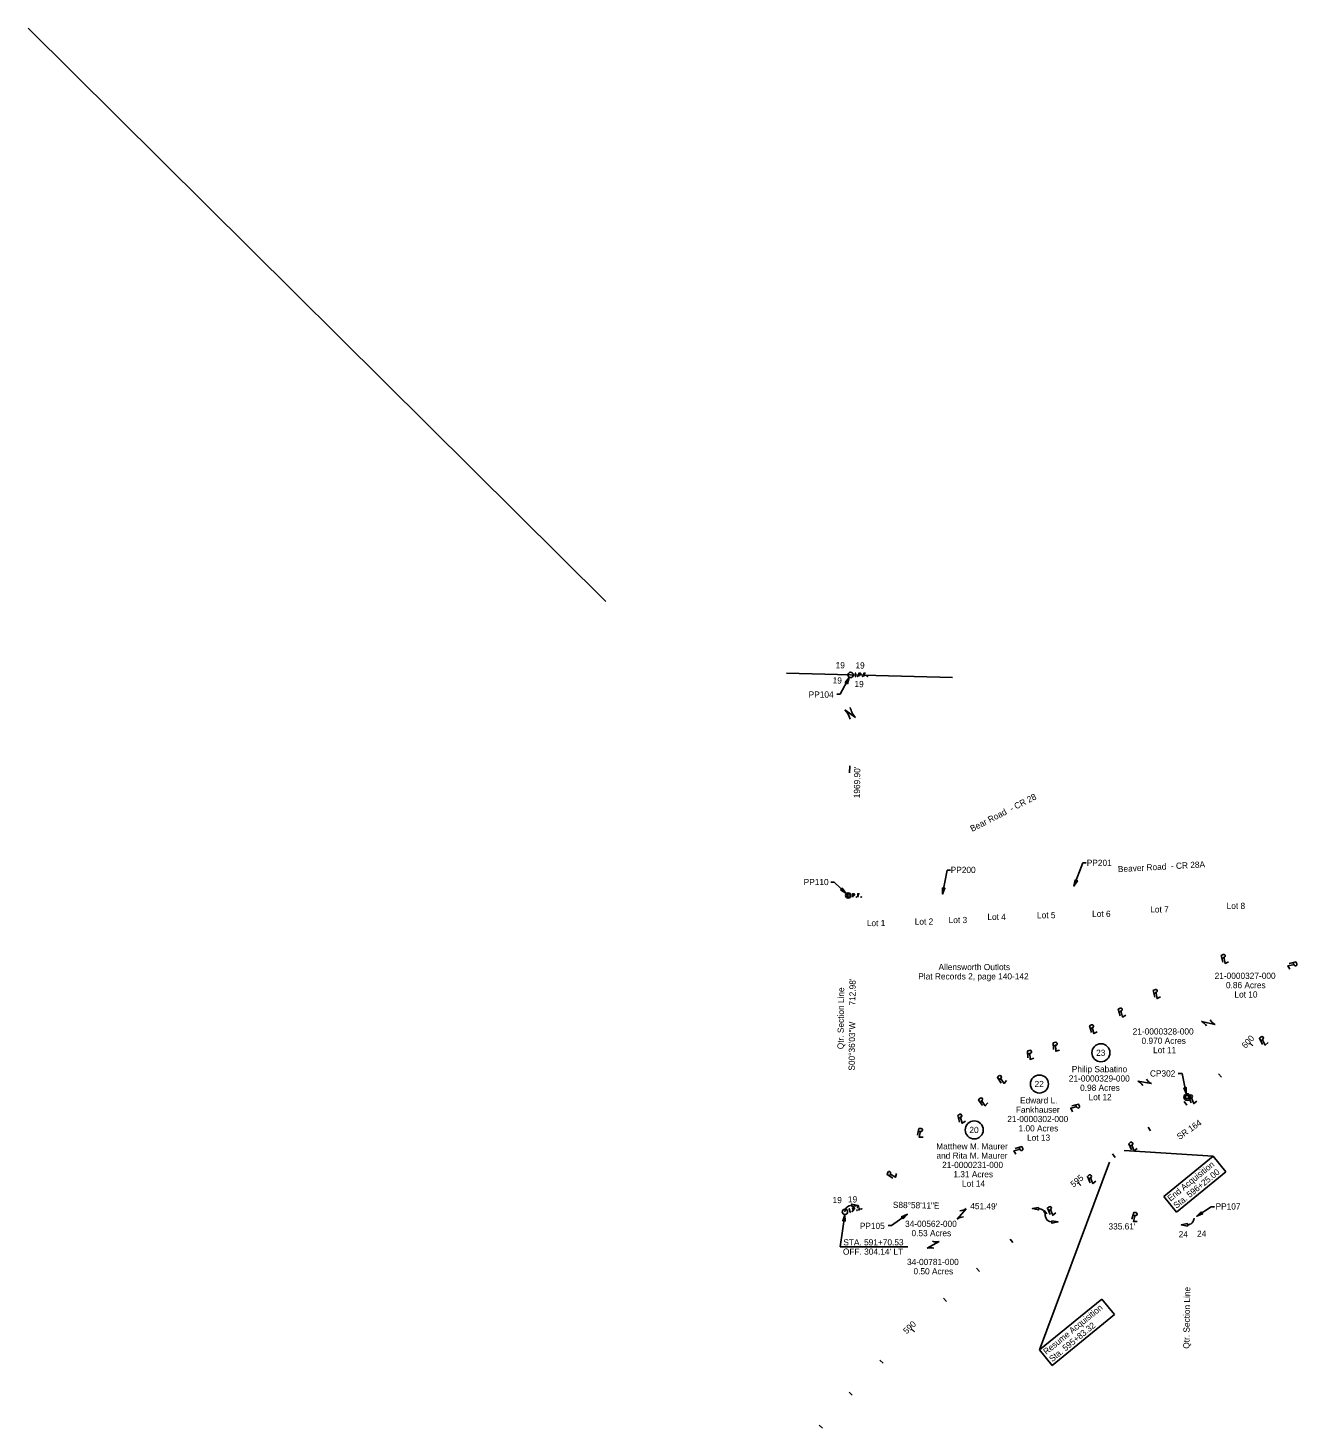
# Model space of a CAD drawing. Extents: x 250163 to 255971, y 441830 to 446572.
# Drawn here: x 250163 to 253023, y 443416 to 446572 of the extents above; entities that cross this region are included whole.
import ezdxf

# ---------------------------------------------------------------- set-up
doc = ezdxf.new("R2010")
doc.units = 0
for name, color, linetype in [('_CIVIL_CONSTRUCTION', 7, 'Continuous'), ('Default', 7, 'Continuous'), ('DV_X_County_Line', 7, 'Continuous'), ('DV_X_Section_VMS_Line', 7, 'Continuous'), ('PF_X_Ground_Line', 7, 'Continuous'), ('RW_P_Esmt_SH', 7, 'Continuous'), ('SH_Text', 7, 'Continuous'), ('SV_X_Text', 7, 'Continuous')]:
    doc.layers.add(name, color=color, linetype=linetype)

msp = doc.modelspace()

# ---------------------------------------------------------------- linework, layer by layer
at = {"layer": '_CIVIL_CONSTRUCTION'}
for p, q in [((252854.2, 444474.2), (252860, 444477.2)), ((252859.2, 444473.3), (252859.2, 444473.3)), ((253013.1, 444460.2), (253013.1, 444460.2)), ((253014, 444465.2), (253017, 444459.4)), ((252701, 444395.2), (252706.8, 444398.1)), ((252706, 444394.2), (252706, 444394.2)), ((252622.4, 444353.1), (252628, 444356.3)), ((252627.4, 444352.4), (252627.4, 444352.4)), ((252808.1, 444332.7), (252838.6, 444325.9)), ((252823.4, 444329.3), (252823.4, 444329.3)), ((252557.7, 444315.6), (252563.3, 444318.8)), ((252562.8, 444314.9), (252562.8, 444314.9)), ((252474.4, 444277.3), (252480.6, 444279.2)), ((252479.2, 444275.5), (252479.2, 444275.5)), ((252941.9, 444288.1), (252946.7, 444292.4)), ((252946.9, 444288.5), (252946.9, 444288.5)), ((252416.5, 444258.8), (252422.6, 444260.8)), ((252421.2, 444257.1), (252421.2, 444257.1)), ((252352.2, 444200.3), (252356.3, 444205.3)), ((252357.1, 444201.4), (252357.1, 444201.4)), ((252664.5, 444198.1), (252695.2, 444192.3)), ((252679.9, 444195.2), (252679.9, 444195.2)), ((252309.6, 444149.6), (252313.8, 444154.6)), ((252314.6, 444150.7), (252314.6, 444150.7)), ((252523.2, 444139.5), (252523.2, 444139.5)), ((252523.9, 444144.5), (252527.1, 444138.9)), ((252781.3, 444156.9), (252786.4, 444160.9)), ((252786.4, 444156.9), (252786.4, 444156.9)), ((252260.6, 444113.7), (252266.2, 444117)), ((252265.6, 444113.1), (252265.6, 444113.1)), ((252169.8, 444084.3), (252176.2, 444084.6)), ((252174, 444081.4), (252174, 444081.4)), ((252395.4, 444043.5), (252395.4, 444043.5)), ((252396, 444048.5), (252399.3, 444042.9)), ((252647.1, 444050.5), (252652.2, 444054.5)), ((252652.2, 444050.5), (252652.2, 444050.5)), ((252105.4, 443983.8), (252107.2, 443990)), ((252109.5, 443986.7), (252109.5, 443986.7)), ((252554, 443976.6), (252559.1, 443980.7)), ((252559.1, 443976.7), (252559.1, 443976.7)), ((252257.3, 443886.9), (252277.7, 443910.5)), ((252267.5, 443898.7), (252267.5, 443898.7)), ((252463.8, 443905.2), (252468.9, 443909.2)), ((252468.8, 443905.2), (252468.8, 443905.2)), ((252653.4, 443894.9), (252659.9, 443894.8)), ((252657.3, 443891.7), (252657.3, 443891.7)), ((252189.8, 443821.3), (252217, 443836.7)), ((252203.4, 443829), (252203.4, 443829))]:
    msp.add_line(p, q, dxfattribs=at)
for points in [[(252856, 444466.2), (252852.7, 444481.1), (252857.3, 444483.5)], [(252858.2, 444478.1), (252861.4, 444463.2), (252869.2, 444467.2)], [(253017.9, 444461.2), (253003, 444457.9), (253007, 444450.1)], [(253005.9, 444463.3), (253020.9, 444466.7), (253023.3, 444462.1)], [(252702.8, 444387.1), (252699.5, 444402.1), (252704.1, 444404.5)], [(252705, 444399.1), (252708.2, 444384.2), (252716, 444388.2)], [(252624.6, 444345.1), (252620.5, 444359.9), (252625, 444362.5)], [(252626.2, 444357.2), (252630.2, 444342.4), (252637.7, 444346.8)], [(252559.9, 444307.7), (252555.9, 444322.4), (252560.3, 444325)], [(252561.5, 444319.7), (252565.5, 444305), (252573.1, 444309.3)], [(252945.6, 444280.8), (252938.7, 444294.5), (252942.5, 444297.9)], [(252416.9, 444250.6), (252416.1, 444265.9), (252421, 444267.5)], [(252474.8, 444269), (252474, 444284.3), (252479, 444285.9)], [(252479, 444280.5), (252479.7, 444265.2), (252488, 444267.8)], [(252944.7, 444292.9), (252951.6, 444279.3), (252958.1, 444285.1)], [(252421, 444262.1), (252421.8, 444246.8), (252430.1, 444249.4)], [(252356.9, 444193.6), (252348.1, 444206.1), (252351.4, 444210.1)], [(252354.3, 444205.5), (252363.1, 444192.9), (252368.7, 444199.6)], [(252314.4, 444142.9), (252305.5, 444155.4), (252308.8, 444159.4)], [(252311.8, 444154.8), (252320.5, 444142.2), (252326.2, 444148.9)], [(252528, 444140.7), (252513.3, 444136.7), (252517.7, 444129.1)], [(252515.9, 444142.3), (252530.7, 444146.4), (252533.3, 444141.9)], [(252784.6, 444149.3), (252778.5, 444163.4), (252782.5, 444166.6)], [(252784.5, 444161.5), (252790.6, 444147.5), (252797.4, 444152.9)], [(252262.9, 444105.8), (252258.6, 444120.5), (252263.1, 444123.2)], [(252264.3, 444117.9), (252268.5, 444103.2), (252276, 444107.6)], [(252168.1, 444076.2), (252171.2, 444091.2), (252176.3, 444091.5)], [(252175, 444086.2), (252171.9, 444071.3), (252180.6, 444071.8)], [(252400.2, 444044.8), (252385.4, 444040.7), (252389.9, 444033.2)], [(252388.1, 444046.3), (252402.8, 444050.5), (252405.5, 444046)], [(252650.4, 444042.9), (252644.3, 444057), (252648.3, 444060.2)], [(252650.3, 444055.1), (252656.3, 444041.1), (252663.2, 444046.5)], [(252112.4, 443979.5), (252099.3, 443987.4), (252100.8, 443992.4)], [(252105.3, 443989.4), (252118.3, 443981.4), (252120.8, 443989.7)], [(252557.3, 443969.1), (252551.1, 443983.1), (252555.2, 443986.4)], [(252557.1, 443981.3), (252563.2, 443967.2), (252570, 443972.7)], [(252467.1, 443897.7), (252460.9, 443911.7), (252465, 443914.9)], [(252466.9, 443909.8), (252473, 443895.8), (252479.8, 443901.2)], [(252651.1, 443887), (252655.3, 443901.7), (252660.5, 443901.6)], [(252658.8, 443896.5), (252654.5, 443881.8), (252663.3, 443881.6)]]:
    msp.add_lwpolyline(points, dxfattribs=at)
for centre, radius, start, end in [((252858.4, 444480.2), 3.45, 297.7561, 108.6133), ((253020, 444461), 3.45, 207.9768, 18.8339), ((252705.2, 444401.2), 3.45, 297.7561, 108.6133), ((252626.2, 444359.3), 3.45, 300.5673, 111.4244), ((252796.2, 444308.9), 26.7, 30.8565, 63.4991), ((252850.5, 444349.8), 26.7, 210.8565, 243.4991), ((252561.6, 444321.8), 3.45, 300.5673, 111.4244), ((252944.4, 444295), 3.45, 312.048, 122.9051), ((252421.6, 444264.1), 3.45, 288.0957, 98.9528), ((252479.5, 444282.5), 3.45, 288.0957, 98.9528), ((252353.7, 444207.5), 3.45, 320.4702, 131.3273), ((252706.3, 444216.6), 26.7, 212.9302, 245.5727), ((252653.5, 444173.8), 26.7, 32.9302, 65.5727), ((252311.1, 444156.8), 3.45, 320.4702, 131.3273), ((252530.1, 444140.7), 3.45, 210.8545, 21.7116), ((252784.3, 444163.6), 3.45, 308.8749, 119.732), ((252264.4, 444120), 3.45, 301.2644, 112.1215), ((252176, 444088.1), 3.45, 273.8756, 84.7328), ((252402.3, 444044.7), 3.45, 210.9924, 21.8495), ((252650, 444057.2), 3.45, 308.8749, 119.732), ((252103.9, 443990.9), 3.45, 344.0044, 154.8615), ((252556.9, 443983.4), 3.45, 308.8749, 119.732), ((252272.7, 443865.1), 26.7, 92.6643, 125.3068), ((252262.3, 443932.3), 26.7, 272.6643, 305.3068), ((252466.7, 443911.9), 3.45, 308.7883, 119.6454), ((252659.9, 443898.2), 3.45, 269.4408, 80.2979), ((252197, 443795.6), 26.7, 72.9148, 105.5574), ((252209.9, 443862.4), 26.7, 252.9148, 285.5574)]:
    msp.add_arc(centre, radius, start, end, dxfattribs=at)
at = {"layer": 'DV_X_County_Line'}
for points in [[(252013.1, 443909.9), (252014.8, 443910.4)], [(252016.1, 443902.5), (252014, 443910.2)], [(252015.2, 443902.2), (252016.9, 443902.7)], [(252020.4, 443904.7), (252020.7, 443904.8), (252020.9, 443904.7), (252021.1, 443904.5), (252021.2, 443904.2), (252021.1, 443903.9), (252021, 443903.8), (252020.7, 443903.7), (252020.5, 443903.8), (252020.3, 443904), (252020.2, 443904.3), (252020.3, 443904.6), (252020.4, 443904.7)], [(252023.6, 443904.5), (252021.5, 443912.2), (252024.1, 443912.9), (252024.4, 443912.9), (252024.8, 443912.9), (252025, 443912.8), (252025.2, 443912.7), (252025.5, 443912.5), (252025.7, 443912.2), (252025.9, 443911.8), (252026.1, 443911.1), (252026.2, 443910.8), (252026.2, 443910.4), (252026.1, 443909.9), (252025.9, 443909.7), (252025.8, 443909.5), (252025.5, 443909.3), (252025.1, 443909.1), (252022.6, 443908.5)], [(252031.3, 443907.7), (252031.6, 443907.8), (252031.7, 443907.7), (252032, 443907.5), (252032.1, 443907.2), (252032, 443906.9), (252031.8, 443906.7), (252031.6, 443906.7), (252031.4, 443906.7), (252031.1, 443906.9), (252031.1, 443907.2), (252031.2, 443907.5), (252031.3, 443907.7)], [(252036.2, 443915.6), (252036.1, 443915.7), (252035.9, 443915.8), (252035.4, 443915.8), (252034.7, 443915.8), (252034.3, 443915.7), (252034.2, 443915.6), (252033.5, 443915.3), (252033, 443914.7), (252032.8, 443914.2), (252032.8, 443913.6), (252032.9, 443913.3), (252033.1, 443912.8), (252033.7, 443912.5), (252037.1, 443911.5), (252037.4, 443911.3), (252037.6, 443911.1), (252037.8, 443910.8), (252037.9, 443910.4), (252038, 443910), (252038, 443909.8), (252038, 443909.4), (252037.9, 443909.2), (252037.9, 443908.9), (252037.7, 443908.7), (252037.6, 443908.6), (252037.4, 443908.4), (252037.3, 443908.3), (252036.8, 443908.1), (252036.1, 443907.9), (252035.6, 443907.9), (252034.8, 443908.1), (252034.2, 443908.4)], [(252041.8, 443910.5), (252042.1, 443910.6), (252042.3, 443910.5), (252042.5, 443910.3), (252042.6, 443910), (252042.5, 443909.7), (252042.4, 443909.6), (252042.1, 443909.5), (252041.9, 443909.6), (252041.7, 443909.8), (252041.6, 443910.1), (252041.7, 443910.4), (252041.8, 443910.5)]]:
    msp.add_lwpolyline(points, dxfattribs=at)
msp.add_circle((252004.4, 443903.4), 6, dxfattribs=at)
at = {"layer": 'DV_X_Section_VMS_Line'}
for p, q in [((251872.6, 445117.6), (252246.6, 445107.6)), ((252015, 444909), (252014.8, 444893.2))]:
    msp.add_line(p, q, dxfattribs=at)
at = {"layer": 'PF_X_Ground_Line'}
for points in [[(252027.2, 445117.7), (252029, 445117.7)], [(252028.1, 445109.7), (252028.1, 445117.7)], [(252035.9, 445109.7), (252035.9, 445117.7), (252038.6, 445117.7), (252038.8, 445117.7), (252039.2, 445117.5), (252039.4, 445117.4), (252039.6, 445117.3), (252039.8, 445117), (252039.9, 445116.6), (252040.1, 445116.1), (252040.1, 445115.4), (252040, 445115.1), (252039.9, 445114.8), (252039.7, 445114.3), (252039.4, 445114.1), (252039.3, 445114), (252039, 445113.9), (252038.6, 445113.8), (252035.9, 445113.8)], [(252051, 445117.7), (252047.2, 445117.7), (252047.2, 445109.7)], [(252027.2, 445109.7), (252029, 445109.7)], [(252032.9, 445110.8), (252033.2, 445110.8), (252033.3, 445110.7), (252033.5, 445110.4), (252033.5, 445110.1), (252033.3, 445109.8), (252033.2, 445109.7), (252032.9, 445109.7), (252032.7, 445109.8), (252032.6, 445110.1), (252032.6, 445110.4), (252032.7, 445110.7), (252032.9, 445110.8)], [(252044.1, 445110.8), (252044.4, 445110.8), (252044.6, 445110.7), (252044.7, 445110.4), (252044.7, 445110.1), (252044.6, 445109.8), (252044.4, 445109.7), (252044.1, 445109.7), (252044, 445109.8), (252043.8, 445110.1), (252043.8, 445110.4), (252044, 445110.7), (252044.1, 445110.8)], [(252047.2, 445113.8), (252049.9, 445113.8)], [(252054.9, 445110.8), (252055.2, 445110.8), (252055.3, 445110.7), (252055.5, 445110.4), (252055.5, 445110.1), (252055.3, 445109.8), (252055.2, 445109.7), (252054.9, 445109.7), (252054.7, 445109.8), (252054.6, 445110.1), (252054.6, 445110.4), (252054.7, 445110.7), (252054.9, 445110.8)], [(252021.9, 444612.4), (252021.9, 444620.4), (252024.6, 444620.4), (252024.8, 444620.3), (252025.2, 444620.2), (252025.4, 444620.1), (252025.5, 444619.9), (252025.8, 444619.6), (252025.9, 444619.3), (252026, 444618.8), (252026, 444618), (252026, 444617.8), (252025.9, 444617.4), (252025.7, 444617), (252025.4, 444616.8), (252025.3, 444616.7), (252025, 444616.5), (252024.6, 444616.5), (252021.9, 444616.5)], [(252030.1, 444613.4), (252030.4, 444613.4), (252030.6, 444613.3), (252030.7, 444613.1), (252030.7, 444612.7), (252030.6, 444612.5), (252030.4, 444612.4), (252030.1, 444612.4), (252030, 444612.5), (252029.8, 444612.7), (252029.8, 444613.1), (252030, 444613.3), (252030.1, 444613.4)], [(252037, 444620.4), (252033.2, 444620.4), (252033.2, 444612.4)], [(252033.2, 444616.5), (252035.9, 444616.5)], [(252040.9, 444613.4), (252041.1, 444613.4), (252041.3, 444613.3), (252041.5, 444613.1), (252041.5, 444612.7), (252041.3, 444612.5), (252041.1, 444612.4), (252040.9, 444612.4), (252040.7, 444612.5), (252040.5, 444612.7), (252040.5, 444613.1), (252040.7, 444613.3), (252040.9, 444613.4)]]:
    msp.add_lwpolyline(points, dxfattribs=at)
for centre, radius in [((252017.1, 445113.7), 6), ((252011.9, 444616.4), 6), ((252011.9, 444616.4), 2.47), ((252775.7, 444162.1), 7.5), ((252775.7, 444162.1), 4)]:
    msp.add_circle(centre, radius, dxfattribs=at)
at = {"layer": 'RW_P_Esmt_SH'}
msp.add_line((252004.4, 445034.6), (252028, 445017.3), dxfattribs=at)
for centre, radius, start, end in [((251967.7, 445000.1), 50.4, 16.1133, 43.2192), ((252070.5, 445053.3), 55.7, 193.5159, 220.2851)]:
    msp.add_arc(centre, radius, start, end, dxfattribs=at)
at = {"layer": 'SH_Text'}
for p, q in [((251465.3, 445279.2), (250162.7, 446571.8)), ((252923.7, 444277.4), (252916.3, 444284.1)), ((252852.9, 444206.8), (252846.3, 444214.3)), ((252775.1, 444144.1), (252769.3, 444152.2)), ((252693.5, 444086.3), (252687.6, 444094.4)), ((252613.8, 444026), (252607.6, 444033.8)), ((252536.2, 443962.9), (252529.7, 443970.5)), ((252459.7, 443898.5), (252453.2, 443906.2)), ((252383.1, 443834.1), (252376.7, 443841.7)), ((252307.5, 443768.7), (252300.9, 443776.1)), ((252233.5, 443701.5), (252226.7, 443708.8)), ((252161, 443632.6), (252154, 443639.7)), ((252090.2, 443562), (252083, 443569)), ((252021, 443489.8), (252013.7, 443496.6)), ((251953.4, 443416.1), (251946, 443422.8))]:
    msp.add_line(p, q, dxfattribs=at)
at = {"layer": 'SV_X_Text'}
for p, q in [((251993.4, 445070.2), (252014.2, 445107.5)), ((251985.9, 445070.2), (251993.4, 445070.2)), ((252520.7, 444637.7), (252540.9, 444690)), ((252540.9, 444690), (252548.3, 444690)), ((251972.3, 444646.8), (251979.8, 444646.8)), ((251979.8, 444646.8), (252006.2, 444621.4)), ((252224.1, 444619.7), (252234.7, 444673.8)), ((252234.7, 444673.8), (252242.2, 444673.8)), ((252755.9, 444215.4), (252764.3, 444215.4)), ((252773.6, 444169.8), (252764.3, 444215.4)), ((252600.7, 444015.6), (252442.7, 443592.1)), ((252633.5, 444041.3), (252834.2, 444028.5)), ((252834.2, 444028.5), (252723, 443938)), ((252862.7, 443993.4), (252834.2, 444028.5)), ((252862.7, 443993.4), (252751.5, 443902.9)), ((252751.5, 443902.9), (252723, 443938)), ((251993.6, 443824.6), (252004, 443896.7)), ((252109, 443872.5), (252145.2, 443898.1)), ((252830.2, 443915), (252797.5, 443893.3)), ((252830.2, 443915), (252837.7, 443915)), ((252101.5, 443872.5), (252109, 443872.5)), ((251993.6, 443824.6), (252146, 443824.6)), ((252442.7, 443592.1), (252583.5, 443706.8)), ((252612, 443671.8), (252583.5, 443706.8)), ((252471.2, 443557.1), (252612, 443671.8)), ((252471.2, 443557.1), (252442.7, 443592.1))]:
    msp.add_line(p, q, dxfattribs=at)
for points in [[(252009.8, 445093.9), (252004.9, 445096.6), (252014.2, 445107.5)], [(252523.1, 444651.7), (252528.3, 444649.7), (252520.7, 444637.7)], [(251994.1, 444629.1), (251998, 444633.1), (252006.2, 444621.4)], [(252224.1, 444634), (252229.6, 444632.9), (252224.1, 444619.7)], [(252768.1, 444182.9), (252773.5, 444184), (252773.6, 444169.8)], [(252019.6, 443915.4), (252019.6, 443921), (252033.6, 443918)], [(252004.8, 443882.5), (251999.3, 443883.3), (252004, 443896.7)], [(252135.4, 443887.7), (252132.1, 443892.3), (252145.2, 443898.1)], [(252441, 443913.4), (252441, 443907.8), (252427, 443910.7)], [(252807.6, 443903.4), (252810.7, 443898.8), (252797.5, 443893.3)], [(252471, 443883.4), (252471, 443877.8), (252485, 443880.7)], [(252776.5, 443871.2), (252776.4, 443876.8), (252762.5, 443873.9)]]:
    msp.add_lwpolyline(points, close=True, dxfattribs=at)
for centre in [(252581.5, 444262), (252442.7, 444191.5), (252295.8, 444088)]:
    msp.add_circle(centre, 20.3, dxfattribs=at)
for centre, start, end in [((252019.4, 443903.2), 89.3991, 178.9698), ((252440.9, 443895.6), 358.9698, 89.3991), ((252470.9, 443895.6), 181.0302, 270.6009), ((252776.3, 443889), 270.6009, 1.0302)]:
    msp.add_arc(centre, 15, start, end, dxfattribs=at)

# ---------------------------------------------------------------- texts
at = {"layer": 'Default'}
for s, rotation, p in [("1969.90'", 89.3991, (252038.3, 444835.5)), ('Bear Road  - CR 28', 27.031, (252291.1, 444759.7)), ('Beaver Road  - CR 28A', 3.2046, (252620.1, 444668.9)), ('S00°36\'03"W       712.98\'', 89.3991, (252026.4, 444221.6)), ('Qtr. Section Line', 89.3991, (252001.3, 444269.8))]:
    msp.add_text(s, height=14, rotation=rotation, dxfattribs=at).set_placement(p)
at = {"layer": 'SV_X_Text'}
for s, rotation, p in [('19', 358.4642, (251983.2, 445128.7)), ('19', 358.4642, (252027.8, 445128.3)), ('19', 358.4642, (251976.5, 445094.5)), ('19', 358.4642, (252025.6, 445086.3)), ('600', 47.8874, (252907.5, 444270.5)), ('SR 164', 34.6802, (252758.6, 444065.2)), ('End Acquisition', 39.1544, (252738.4, 443926.2)), ('595', 40.0802, (252519.8, 443957.7)), ('Sta. 596+25.00', 39.1544, (252751.8, 443910)), ('19', 358.9698, (251976.4, 443923.2)), ('19', 358.9698, (252011, 443924.7)), ('S88°58\'11"E', 358.9698, (252112.3, 443912.2)), ("451.49'", 358.9698, (252286.7, 443909.6)), ('Qtr. Section Line', 89.1784, (252780.9, 443594.7)), ('Resume Acquisition', 39.1544, (252458.5, 443580.6)), ('590', 44.2202, (252143.7, 443627)), ('Sta. 595+83.32', 39.1544, (252471.7, 443564.3))]:
    msp.add_text(s, height=14, rotation=rotation, dxfattribs=at).set_placement(p)
for s, p in [('PP104', (251922.6, 445062.4)), ('PP200', (252242.8, 444667.2)), ('PP201', (252549.6, 444683.1)), ('PP110', (251911.3, 444639.8)), ('Lot 6', (252561.6, 444568.2)), ('Lot 7', (252692.6, 444578.1)), ('Lot 8', (252864.9, 444586)), ('Lot 1', (252053.7, 444547.3)), ('Lot 2', (252161.7, 444550.7)), ('Lot 3', (252238.2, 444554.2)), ('Lot 4', (252325.5, 444561.2)), ('Lot 5', (252437.4, 444565.1)), ('Allensworth Outlots', (252215.4, 444448.2)), ('Plat Records 2, page 140-142', (252169.7, 444427.2)), ('21-0000327-000', (252837.8, 444428.4)), ('0.86 Acres', (252863.3, 444407.4)), ('Lot 10', (252882.4, 444386.4)), ('21-0000328-000', (252653, 444303)), ('0.970 Acres', (252673, 444282)), ('23', (252570.6, 444255)), ('Lot 11', (252699.1, 444261)), ('Philip Sabatino', (252515.8, 444218)), ('21-0000329-000', (252509, 444197)), ('CP302', (252691.9, 444208.3)), ('22', (252431.8, 444184.5)), ('0.98 Acres', (252534.5, 444176)), ('Fankhauser', (252389.6, 444126.6)), ('Edward L.', (252399.1, 444147.6)), ('Lot 12', (252553.6, 444155)), ('21-0000302-000', (252370.3, 444105.6)), ('20', (252284.9, 444081)), ('1.00 Acres', (252395.7, 444084.6)), ('Lot 13', (252414.9, 444063.6)), ('Matthew M. Maurer', (252210.1, 444044.1)), ('and Rita M. Maurer', (252210.7, 444023.1)), ('21-0000231-000', (252223.4, 444002.1)), ('1.31 Acres', (252248.8, 443981.1)), ('Lot 14', (252268.2, 443960.1)), ('PP107', (252839.9, 443908.5)), ('PP105', (252037.9, 443864.7)), ('34-00562-000', (252139.9, 443869.4)), ('0.53 Acres', (252154.4, 443848.4)), ("335.61'", (252598.5, 443863.6)), ('24', (252756.7, 443845.7)), ('24', (252798.1, 443847.1)), ('STA. 591+70.53', (252000.7, 443827.7)), ("OFF. 304.14' LT", (251999.8, 443806.7)), ('34-00781-000', (252144.3, 443783.4)), ('0.50 Acres', (252158.9, 443762.4))]:
    msp.add_text(s, height=14, dxfattribs=at).set_placement(p)

doc.saveas('drawing.dxf')
